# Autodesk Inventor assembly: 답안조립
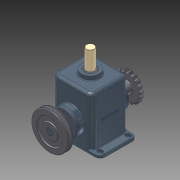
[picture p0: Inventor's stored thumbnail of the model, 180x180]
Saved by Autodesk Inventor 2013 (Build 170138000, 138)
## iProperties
Created: 2015-03
Part Number: 답안조립
Document SubType Name: Assembly
Designer: Administrator
Mass: 8578.96 g
Surface Area: 4386.43 cm^2
Volume: 1982.5 cm^3
Density: 4.32735 g/cm^3
Author: Administrator
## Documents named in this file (15)
- C:\Users\Administrator\Desktop\350306V1031\답안조립.iam
- C:\Users\Administrator\Desktop\350306V1031\본체.ipt
- C:\Users\Administrator\Desktop\350306V1031\M4x0.5.ipt
- C:\Users\Administrator\Desktop\350306V1031\V-벨트풀리.ipt
- C:\Users\Administrator\Desktop\350306V1031\멈춤링.ipt
- C:\Users\Administrator\Desktop\350306V1031\베어링 6205.ipt
- C:\Users\Administrator\Desktop\350306V1031\오일실.ipt
- C:\Users\Administrator\Desktop\350306V1031\커버.ipt
- C:\Users\Administrator\Desktop\350306V1031\키 8x8.ipt
- C:\Users\Administrator\Desktop\350306V1031\편심축.ipt
- C:\Users\Administrator\Desktop\350306V1031\가변스프링.ipt
- C:\Users\Administrator\Desktop\350306V1031\부시.ipt
- C:\Users\Administrator\Desktop\350306V1031\슬라이드.ipt
- C:\Users\Administrator\Desktop\350306V1031\체인 스프로킷.ipt
- C:\Users\Administrator\Desktop\350306V1031\멈춤나사 M5x0.5.ipt
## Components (9 placed, 4 different names)
1. V-벨트풀리:1 — 각도:4, 플러쉬:1
2. 가변스프링:1 — 각도:6
3. 5-체인 스프로킷:1 — 각도:7, 플러쉬:2
4. M4x0.5:1
5. M4x0.5:2
6. M4x0.5:3
7. M4x0.5:4
8. M4x0.5:5
9. M4x0.5:6
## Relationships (5: Angle 3, Flush 2)
- 각도:4 [Angle]: V-벨트풀리:1
- 플러쉬:1 [Flush]: V-벨트풀리:1
- 각도:6 [Angle]: 가변스프링:1
- 각도:7 [Angle]: 5-체인 스프로킷:1
- 플러쉬:2 [Flush]: 5-체인 스프로킷:1
